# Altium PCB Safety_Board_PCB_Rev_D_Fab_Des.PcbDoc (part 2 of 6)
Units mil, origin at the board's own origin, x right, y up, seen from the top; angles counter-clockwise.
Board outline 11000 x 4400 mil, 6 copper layers (L1-TOP, L2-Plane, L3-Signal, L4-Signal, L5-Plane, L6-BOT); 712 components, 540 nets, 2214 pads, 875 vias.
Unrouted connection lines stored in the file: 3.
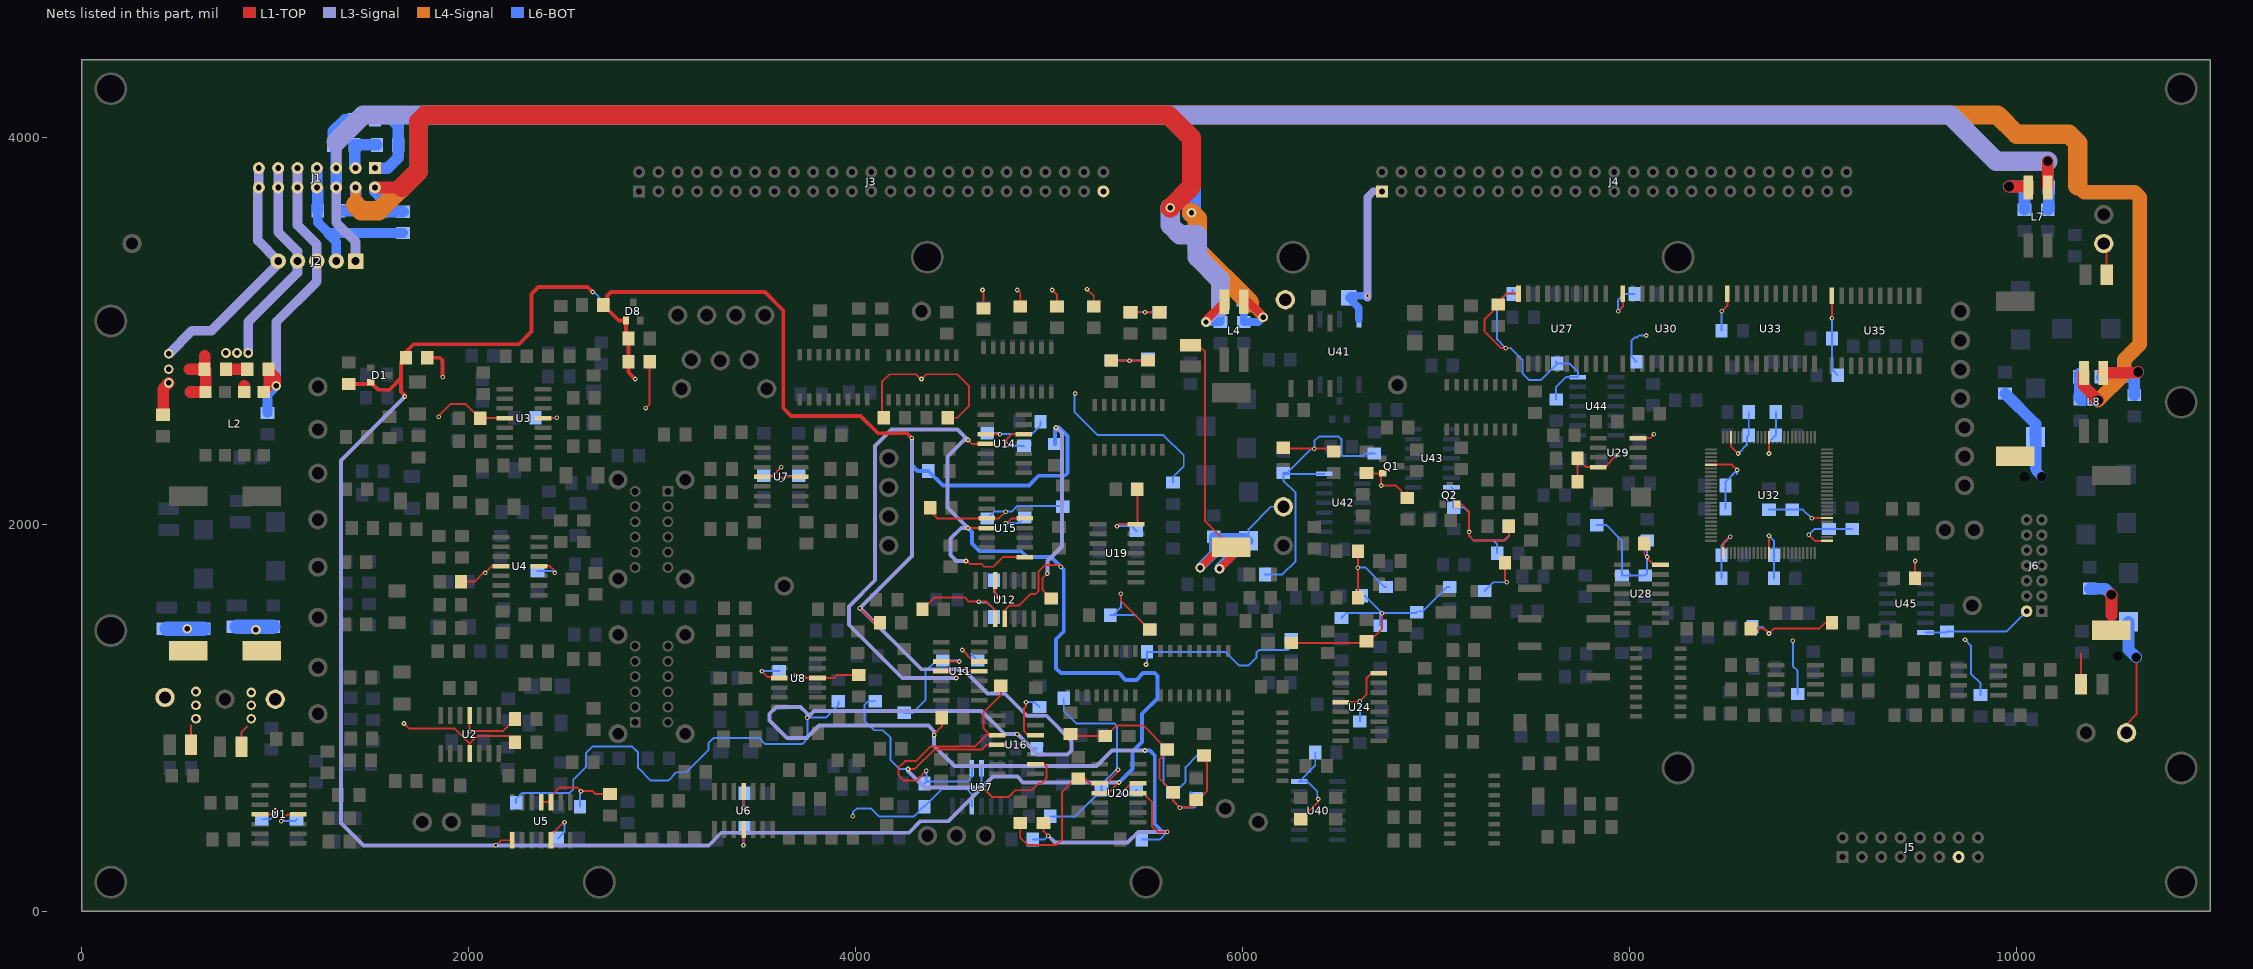
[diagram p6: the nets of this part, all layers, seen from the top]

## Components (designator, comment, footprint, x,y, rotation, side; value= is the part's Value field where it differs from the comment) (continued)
R348 "2000" 1206 7720,1330 r0 bottom locked (schematic designator R154)
R349 "2000" 1206 7720,1211.26 r0 bottom locked (schematic designator R156)
R350 "205" 1206 7760,935 r180 bottom locked (schematic designator R47)
R351 "205" 1206 7760,815 r180 bottom locked (schematic designator R46)
R352 "205" 1206 7850,555 r180 bottom locked (schematic designator R45)
R353 "205" 1206 7850,435 r180 bottom locked (schematic designator R44)
R354 "10000" 1206 7830,2050 r270 bottom locked (schematic designator R179)
R355 "10000" 1206 7960,1680 r90 bottom locked (schematic designator R150)
R356 "100" 1206 7960,1390 r270 bottom locked (schematic designator R158)
R357 "100" 1206 8050,2380 r90 bottom locked (schematic designator R212)
R358 "10000" 1206 8090,1970 r270 bottom locked (schematic designator R188)
R359 "10000" 1206 8090,2840 r180 bottom locked (schematic designator R223)
R360 "100" 1206 8120,2670 r270 bottom locked (schematic designator R242)
R361 "10000" 1206 8080,1680 r90 bottom locked (schematic designator R153)
R362 "100" 1206 8080,1390 r270 bottom locked (schematic designator R159)
R363 "0_jumper" 1206 8697.96,1256.92 r0 bottom locked (schematic designator R134)
R364 "2000" 1206 8517.96,1076.92 r270 bottom locked (schematic designator R155)
R365 "10000" 1206 8580,1470 r0 bottom locked (schematic designator R326)
R366 "0_jumper" 1206 8747.96,1076.92 r90 bottom locked (schematic designator R132)
R367 "100" 1206 8800,2840 r180 bottom locked (schematic designator R240)
R368 "6810" 1206 8870,1540 r180 bottom locked (schematic designator R329)
R369 "0_jumper" 1206 8867.96,1066.92 r90 bottom locked (schematic designator R128)
R370 "0_jumper" 1206 8947.96,1286.92 r90 bottom locked (schematic designator R137)
R371 "10000" 1206 9020,2770 r0 bottom locked (schematic designator R221)
R372 "6810" 1206 9100,1490 r180 bottom locked (schematic designator R272)
R373 "0_jumper" 1206 9177.96,1246.92 r180 bottom locked (schematic designator R136)
R374 "0_jumper" 1206 9210,2920 r0 bottom locked (schematic designator R361)
R375 "0_jumper" 1206 9177.96,1131.92 r180 bottom locked (schematic designator R135)
R376 "0_jumper" 1206 9430,2920 r180 bottom locked (schematic designator R344)
R377 "0_jumper" 1206 9637.96,1256.92 r0 bottom locked (schematic designator R144)
R378 "2000" 1206 9462.96,1071.92 r270 bottom locked (schematic designator R157)
R379 "0_jumper" 1206 9692.96,1071.92 r90 bottom locked (schematic designator R142)
R380 "0_jumper" 1206 9812.96,1061.92 r90 bottom locked (schematic designator R138)
R381 "0_jumper" 1206 9892.96,1281.92 r90 bottom locked (schematic designator R147)
R382 "3.01" 1206 9940,2730 r270 bottom locked (schematic designator R18)
R383 "0_jumper" 1206 10040,3570 r270 bottom locked (schematic designator R8)
R384 "0_jumper" 1206 10117.96,1246.92 r180 bottom locked (schematic designator R146)
R385 "0_jumper" 1206 10122.96,1131.92 r180 bottom locked (schematic designator R145)
R386 "0_jumper" 1206 10160,3570 r270 bottom locked (schematic designator R6)
R387 "249" 1206 10300,3440 r270 bottom locked (schematic designator R405)
R388 "0_jumper" 1206 10330,2590 r270 bottom locked (schematic designator R4)
R389 "3.01" 1206 10377.96,1721.92 r270 bottom locked (schematic designator R17)
R390 "249" 1206 10337.96,1391.92 r270 bottom locked (schematic designator R404)
R391 "0_jumper" 1206 10607.96,2611.92 r270 bottom locked (schematic designator R3)
SW1 "MSS420004" MSS420004 2944.65,1973.11 r270 top locked
SW2 "MSS420004" MSS420004 2944.65,1173.11 r90 top locked
SW3 "TL6120AF300QG" SWITCH_TL6120AF300QG 7660,1590 r270 top locked
SW4 "TL6120AF300QG" SWITCH_TL6120AF300QG 7660,1290 r90 top locked
TP1 "TP_5006" TP_COMPACT 260,3450 r0 top locked (schematic designator TP54)
TP2 "TP_5005" TP_COMPACT 430,1105 r0 top locked
TP3 "TP_5006" TP_COMPACT 740,1095 r0 top locked (schematic designator TP6)
TP4 "TP_5005" TP_COMPACT 1000,1095 r0 top locked (schematic designator TP1)
TP5 "TP_5009" TP_COMPACT 1220,2710 r0 top locked (schematic designator TP11)
TP6 "TP_5008" TP_COMPACT 1220,2490 r0 top locked (schematic designator TP13)
TP7 "TP_5009" TP_COMPACT 1220,2263.11 r0 top locked (schematic designator TP12)
TP8 "TP_5008" TP_COMPACT 1220,2023.11 r0 top locked (schematic designator TP14)
TP9 "TP_5009" TP_COMPACT 1220,1778.11 r0 top locked (schematic designator TP15)
TP10 "TP_5008" TP_COMPACT 1220,1518.11 r0 top locked (schematic designator TP17)
TP11 "TP_5009" TP_COMPACT 1220,1260 r0 top locked (schematic designator TP16)
TP12 "TP_5008" TP_COMPACT 1220,1020 r0 top locked (schematic designator TP18)
TP13 "TP_5007" TP_COMPACT 1760,460 r90 top locked (schematic designator TP28)
TP14 "TP_5007" TP_COMPACT 1910,460 r90 top locked (schematic designator TP31)
TP15 "TP_5007" TP_COMPACT 3080,3080 r0 top locked (schematic designator TP25)
TP16 "TP_5007" TP_COMPACT 3100,2700 r0 top locked (schematic designator TP48)
TP17 "TP_5007" TP_COMPACT 3230,3080 r0 top locked (schematic designator TP19)
TP18 "TP_5007" TP_COMPACT 3150,2850 r0 top locked (schematic designator TP41)
TP19 "TP_5007" TP_COMPACT 3300,2845 r0 top locked (schematic designator TP44)
TP20 "TP_5007" TP_COMPACT 3380,3080 r0 top locked (schematic designator TP35)
TP21 "TP_5007" TP_COMPACT 3530,3080 r0 top locked (schematic designator TP38)
TP22 "TP_5007" TP_COMPACT 3450,2850 r0 top locked (schematic designator TP23)
TP23 "TP_5007" TP_COMPACT 3540,2700 r0 top locked (schematic designator TP49)
TP24 "TP_5006" TP_COMPACT 3630,1680 r0 top locked (schematic designator TP32)
TP25 "TP_5007" TP_COMPACT 4170,2340 r0 top locked (schematic designator TP7)
TP26 "TP_5007" TP_COMPACT 4170,2190 r0 top locked (schematic designator TP21)
TP27 "TP_5007" TP_COMPACT 4170,2040 r0 top locked (schematic designator TP34)
TP28 "TP_5007" TP_COMPACT 4170,1890 r0 top locked (schematic designator TP37)
TP29 "TP_5006" TP_COMPACT 4340,3100 r0 top locked (schematic designator TP27)
TP30 "TP_5007" TP_COMPACT 4370,390 r0 top locked (schematic designator TP22)
TP31 "TP_5007" TP_COMPACT 4520,390 r0 top locked (schematic designator TP40)
TP32 "TP_5007" TP_COMPACT 4670,390 r0 top locked (schematic designator TP43)
TP33 "TP_5006" TP_COMPACT 5910,530 r0 top locked (schematic designator TP51)
TP34 "TP_5006" TP_COMPACT 6080,460 r0 top locked (schematic designator TP52)
TP35 "TP_5006" TP_COMPACT 6220,3160 r0 top locked (schematic designator TP55)
TP36 "TP_5005" TP_COMPACT 6210,2090 r90 top locked (schematic designator TP5)
TP37 "TP_5006" TP_COMPACT 6210,1890 r0 top locked (schematic designator TP10)
TP38 "TP_5006" TP_COMPACT 6800,2720 r180 top locked (schematic designator TP29)
TP39 "TP_5007" TP_COMPACT 9630,1970 r0 top locked (schematic designator TP30)
TP40 "TP_5007" TP_COMPACT 9710,3100 r0 top locked (schematic designator TP20)
TP41 "TP_5007" TP_COMPACT 9710,2950 r0 top locked (schematic designator TP26)
TP42 "TP_5007" TP_COMPACT 9710,2800 r0 top locked (schematic designator TP46)
TP43 "TP_5007" TP_COMPACT 9710,2650 r0 top locked (schematic designator TP47)
TP44 "TP_5007" TP_COMPACT 9730,2500 r0 top locked (schematic designator TP24)
TP45 "TP_5007" TP_COMPACT 9730,2350 r0 top locked
TP46 "TP_5007" TP_COMPACT 9730,2200 r0 top locked (schematic designator TP42)
TP47 "TP_5007" TP_COMPACT 9780,1970 r0 top locked (schematic designator TP33)
TP48 "TP_5006" TP_COMPACT 9770,1580 r0 top locked (schematic designator TP53)
TP49 "TP_5006" TP_COMPACT 10357.97,921.92 r0 top locked (schematic designator TP8)
TP50 "TP_5006" TP_COMPACT 10450,3600 r0 top locked (schematic designator TP9)
TP51 "TP_5005" TP_COMPACT 10450,3450 r90 top locked (schematic designator TP4)
TP52 "TP_5005" TP_COMPACT 10567.97,921.92 r0 top locked (schematic designator TP3)
U1 "OPA4277UA" SOIC_14_Narrow 1020,500 r270 top locked (schematic designator U29)
U2 "OPA4277UA" SOIC_14_Narrow 2004.65,913.11 r0 top locked (schematic designator U8)
U3 "OPA4277UA" SOIC_14_Narrow 2284.65,2548.11 r270 top locked (schematic designator U5)
U4 "OPA4277UA" SOIC_14_Narrow 2264.65,1783.11 r270 top locked (schematic designator U6)
U5 "LM339DR2G" SOIC_14_Narrow 2375,465 r180 top locked (schematic designator U31)
U6 "OPA4277UA" SOIC_14_Narrow 3420,520 r0 top locked (schematic designator U41)
U7 "OPA4277UA" SOIC_14_Narrow 3615,2245 r270 top locked (schematic designator U35)
U8 "OPA4277UA" SOIC_14_Narrow 3703.43,1205 r270 top locked (schematic designator U7)
U9 "TLP281-4" SOIC_16_C5.85 3885,2760 r180 top locked (schematic designator U24)
U10 "TLP281-4" SOIC_16_C5.85 4345,2758 r180 top locked (schematic designator U25)
U11 "LM339DR2G" SOIC_14_Narrow 4540,1240.12 r270 top locked (schematic designator U33)
U12 "LM339DR2G" SOIC_14_Narrow 4770,1610 r0 top locked (schematic designator U39)
U13 "TLP281-4" SOIC_16_C5.85 4835,2795 r180 top locked (schematic designator U18)
U14 "LM339DR2G" SOIC_14_Narrow 4770,2415 r270 top locked (schematic designator U32)
U15 "LM339DR2G" SOIC_14_Narrow 4775,1980 r270 top locked (schematic designator U42)
U16 "LM339DR2G" SOIC_14_Narrow 4830,860 r270 top locked (schematic designator U36)
U17 "TLP281-4" SOIC_16_C5.85 5270,1230 r0 top locked (schematic designator U40)
U18 "TLP281-4" SOIC_16_C5.85 5410,2500 r180 top locked (schematic designator U19)
U19 "M74HC14RM13TR" SOIC_14_Narrow 5350,1850 r270 top locked (schematic designator U26)
U20 "LM339DR2G" SOIC_14_Narrow 5360,610 r270 top locked (schematic designator U38)
U21 "TLP281-4" SOIC_16_C5.85 5750,1230 r0 top locked (schematic designator U34)
U22 "TLP281-4" SOIC_16_C5.85 6090,850 r270 top locked (schematic designator U28)
U23 "PS710EL-1A-A" SO_6_254P 6400,2870 r0 top locked (schematic designator U17)
U24 "DS26LS32ACM" SOIC_16_NARROW 6605,1055 r270 top locked (schematic designator U4)
U25 "TLP281-4" SOIC_16_C5.85 7230,2605 r0 top locked (schematic designator U15)
U26 "TLP281-4" SOIC_16_C5.85 7185,525 r90 top locked (schematic designator U3)
U27 "M74HCT541M1R" SOIC_20_WIDE 7650,3010 r0 top locked (schematic designator U44)
U28 "M74HC14RM13TR" SOIC_14_Narrow 8060,1640 r270 top locked (schematic designator U14)
U29 "TS555IDT" SOIC_8_NARROW 7939.96,2370.04 r90 top locked (schematic designator U9)
U30 "M74HCT541M1R" SOIC_20_WIDE 8190,3010 r0 top locked (schematic designator U45)
U31 "TLP281-4" SOIC_16_C5.85 8147.96,1181.92 r270 top locked (schematic designator U11)
U32 "XC9572-15TQ100C" TQ100 8720,2150 r0 top locked (schematic designator U10)
U33 "M74HCT541M1R" SOIC_20_WIDE 8730,3010 r0 top locked (schematic designator U43)
U34 "MAX1232ESA+" SOIC_8_NARROW 8857.96,1196.92 r90 top locked (schematic designator U12)
U35 "M74HCT541M1R" SOIC_20_WIDE 9270,3000 r0 top locked (schematic designator U46)
U36 "MAX1232ESA+" SOIC_8_NARROW 9802.96,1191.92 r90 top locked (schematic designator U13)
U37 "LM339DR2G" SOIC_14_Narrow 4650,640 r0 bottom locked (schematic designator U47)
U38 "TLP281-4" SOIC_16_C5.85 4835,2810 r0 bottom locked (schematic designator U23)
U39 "TLP281-4" SOIC_16_C5.85 5410,2500 r0 bottom locked (schematic designator U20)
U40 "M74HC14RM13TR" SOIC_14_Narrow 6390,520 r270 bottom locked (schematic designator U30)
U41 "PS710EL-1A-A" SO_6_254P 6450,2890 r180 bottom locked (schematic designator U16)
U42 "M74HC14RM13TR" SOIC_14_Narrow 6520,2110 r270 bottom locked (schematic designator U21)
U43 "M74HC14RM13TR" SOIC_14_Narrow 6980,2340 r90 bottom locked (schematic designator U27)
U44 "M74HC14RM13TR" SOIC_14_Narrow 7830,2610 r270 bottom locked (schematic designator U22)
U45 "M74HC14RM13TR" SOIC_14_Narrow 9430,1590 r90 bottom locked (schematic designator U37)

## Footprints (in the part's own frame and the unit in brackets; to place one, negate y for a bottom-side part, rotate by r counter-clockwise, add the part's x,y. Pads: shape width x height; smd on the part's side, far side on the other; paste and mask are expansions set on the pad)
1-5499923-0 [mil] "Header, 50 pin, male, 2x25, shrouded, latch, vertical"
  rect 62x62 hole 30: 1(0,0)
  round 62 hole 30: 2(100,0) 3(0,-100) 4(100,-100) 5(0,-200) 6(100,-200) 7(0,-300) 8(100,-300) 9(0,-400) 10(100,-400) 11(0,-500) 12(100,-500) 13(0,-600) 14(100,-600) 15(0,-700) 16(100,-700) 17(0,-800) 18(100,-800) 19(0,-900) 20(100,-900) 21(0,-1000) 22(100,-1000) 23(0,-1100) 24(100,-1100) 25(0,-1200) 26(100,-1200) 27(0,-1300) 28(100,-1300) 29(0,-1400) 30(100,-1400) 31(0,-1500) 32(100,-1500) 33(0,-1600) 34(100,-1600) 35(0,-1700) 36(100,-1700) 37(0,-1800) 38(100,-1800) 39(0,-1900) 40(100,-1900) 41(0,-2000) 42(100,-2000) 43(0,-2100) 44(100,-2100) 45(0,-2200) 46(100,-2200) 47(0,-2300) 48(100,-2300) 49(0,-2400) 50(100,-2400)
  silkscreen extent -150,-2850 250,450
22-23-2051 [mil] "Header, 5 pin male, vertical (IRTF power connector)"
  rect 80x80 hole 40: 1(0,-200)
  round 80 hole 40: 2(0,-100) 3(0,0) 4(0,100) 5(0,200)
  silkscreen extent -130,-260 130,260
1206 [mm]
  rect 1.6x1.8 smd: 1(-1.4,0) 2(1.4,0)
  silkscreen extent -2.6,-1.3 2.6,1.3
1210 [mm]
  rect 1.6x2.7 smd: 1(-1.4,0) 2(1.4,0)
  silkscreen extent -2.6,-1.75 2.6,1.75
5000_inductor [mil] "Inductor, Common Mode"
  rect 125x50 smd: 1(-150,50) 2(-150,-50) 3(150,-50) 4(150,50)
  silkscreen extent -230,-125 230,170
5000_INDUCTOR [mil] "Inductor, Common Mode"
  rect 125x50 smd: 1(-150,50) 2(-150,-50) 3(150,-50) 4(150,50)
  silkscreen extent -230,-125 230,170
8532_inductor [mil] "Inductor, 8532 series"
  rect 100x200 smd: 1(-400,0) 2(400,0)
  silkscreen extent -470,-180 470,180
5499922-2 [mil] "Header, 14 pin, male, 2x7, shrouded, latch, vertical"
  rect 62x62 hole 30: 1(0,0)
  round 62 hole 30: 2(100,0) 3(0,-100) 4(100,-100) 5(0,-200) 6(100,-200) 7(0,-300) 8(100,-300) 9(0,-400) 10(100,-400) 11(0,-500) 12(100,-500) 13(0,-600) 14(100,-600)
  silkscreen extent -150,-1050 250,450
5499922-3 [mil] "Header, 16 pin, male, 2x8, shrouded, latch, vertical"
  rect 62x62 hole 30: 1(0,0)
  round 62 hole 30: 2(100,0) 3(0,-100) 4(100,-100) 5(0,-200) 6(100,-200) 7(0,-300) 8(100,-300) 9(0,-400) 10(100,-400) 11(0,-500) 12(100,-500) 13(0,-600) 14(100,-600) 15(0,-700) 16(100,-700)
  silkscreen extent -150,-1150 250,450
CAP_EIA_6032 [mm]
  rect 2.6x2.5 smd: 1(-2.5,0) 2(2.5,0)
  silkscreen extent -5.2,-1.78 4.2,1.78
CAP_EIA_7343 [mm]
  rect 2.6x2.5 smd: 1(-3.2,0) 2(3.2,0)
  silkscreen extent -5.9,-2.45 4.9,2.45
"DO-214AA (SMB) & MARKING" [mm]
  rect 1.7x2.2 smd: A(-2.1,0) K(2.1,0)
  silkscreen extent -3.17,-2.03 3.17,3.68
"DO-214AC (SMA)" [mil] "SMA"
  rect 80x80 smd: A(-78.5,0) K(78.5,0)
  silkscreen extent -130,-60 130,60
HDR_87831-1420 [mil] "Header, 7x2, straight, shroud, common use for JTAG"
  rect 60x60 hole 28: 1(0,0)
  round 60 hole 28: 2(78.74,0) 3(0,-78.74) 5(0,-157.48) 6(78.74,-157.48) 7(0,-236.22) 8(78.74,-236.22) 9(0,-314.96) 10(78.74,-314.96) 11(0,-393.7) 12(78.74,-393.7) 13(0,-472.44) 14(78.74,-472.44)
  round 59.06 hole 28: 4(78.74,-78.74)
  silkscreen extent -98,-571 177,98
LED_1210 [mm] "LED, 1210 case"
  rect 1.6x2.7 smd: A(-1.4,0) K(1.4,0)
  silkscreen extent -2.6,-1.78 2.6,1.78
MSS420004 [mm] "Switch, Slide, 4PDT"
  rect 1.422x1.422 hole 0.914: 1(-5,2.15)
  round 1.422 hole 0.914: 2(-3,2.15) 3(-1,2.15) 4(1,2.15) 5(3,2.15) 6(5,2.15) 7(-5,-2.15) 8(-3,-2.15) 9(-1,-2.15) 10(1,-2.15) 11(3,-2.15) 12(5,-2.15)
  round 2.5 hole 1.5: ""(-6.5,4.4) ""(-6.5,-4.4) ""(6.5,4.4) ""(6.5,-4.4)
  silkscreen extent -8,-5.5 8,5.5
SO_6_254P [mm] "Surface mount, 6 pin, 2.54mm spacing"
  rect 0.65x2.2 smd: 1(-3.81,-4.3) 2(-1.27,-4.3) 3(1.27,-4.3) 4(1.27,4.3) 5(-1.27,4.3) 6(-3.81,4.3)
  silkscreen extent -6,-4.42 3.5,2.8
SOIC_8_NARROW [mm] "8 pin Narrow SOIC"
  rect 0.6x2.2 smd: 1(-1.905,-2.6) 2(-0.635,-2.6) 3(0.635,-2.6) 4(1.905,-2.6) 5(1.905,2.6) 6(0.635,2.6) 7(-0.635,2.6) 8(-1.905,2.6)
  silkscreen extent -2.88,-2.72 2.5,1.1
SOIC_14_Narrow [mm] "14 pin Narrow SOIC"
  rect 0.6x2.2 smd: 1(-3.81,-2.5) 2(-2.54,-2.5) 3(-1.27,-2.5) 4(0,-2.5) 5(1.27,-2.5) 6(2.54,-2.5) 7(3.81,-2.5) 8(3.81,2.5) 9(2.54,2.5) 10(1.27,2.5) 11(0,2.5) 12(-1.27,2.5) 13(-2.54,2.5) 14(-3.81,2.5)
  silkscreen extent -4.78,-2.62 4.38,1
SOIC_16_C5.85 [mm]
  rect 0.6x1.55 smd: 1(-4.445,-2.925) 2(-3.175,-2.925) 3(-1.905,-2.925) 4(-0.635,-2.925) 5(0.635,-2.925) 6(1.905,-2.925) 7(3.175,-2.925) 8(4.445,-2.925) 9(4.445,2.925) 10(3.175,2.925) 11(1.905,2.925) 12(0.635,2.925) 13(-0.635,2.925) 14(-1.905,2.925) 15(-3.175,2.925) 16(-4.445,2.925)
  silkscreen extent -5.4,-3.05 5,1.75
SOIC_16_NARROW [mm] "16 pin Narrow SOIC"
  rect 0.6x2.2 smd: 1(-4.445,-2.5) 2(-3.175,-2.5) 3(-1.905,-2.5) 4(-0.635,-2.5) 5(0.635,-2.5) 6(1.905,-2.5) 7(3.175,-2.5) 8(4.445,-2.5) 9(4.445,2.5) 10(3.175,2.5) 11(1.905,2.5) 12(0.635,2.5) 13(-0.635,2.5) 14(-1.905,2.5) 15(-3.175,2.5) 16(-4.445,2.5)
  silkscreen extent -5.42,-2.62 5,1
SOIC_20_WIDE [mm] "Small Outline; 20 Leads; Body Width 7.5 mm; Pitch 1.27 mm"
  rect 0.6x2.2 smd: 1(-5.715,-4.6) 2(-4.445,-4.6) 3(-3.175,-4.6) 4(-1.905,-4.6) 5(-0.635,-4.6) 6(0.635,-4.6) 7(1.905,-4.6) 8(3.175,-4.6) 9(4.445,-4.6) 10(5.715,-4.6) 11(5.715,4.6) 12(4.445,4.6) 13(3.175,4.6) 14(1.905,4.6) 15(0.635,4.6) 16(-0.635,4.6) 17(-1.905,4.6) 18(-3.175,4.6) 19(-4.445,4.6) 20(-5.715,4.6)
  silkscreen extent -6.69,-4.72 6.53,3.1
SOT23 [mm]
  rect 0.85x1 smd: 1(-0.95,-1.2) 2(0.95,-1.2) 3(0,1.2)
  silkscreen extent -2.05,-1.32 1.28,1.2
SWITCH_TL6120AF300QG [mm] "Switch, Tactile, SPST, NO"
  rect 1x3.1 smd: 1(2,4.5) 2(-2,4.5) 3(2,-4.5) 4(-2,-4.5)
  silkscreen extent -3.6,-3.6 3.6,3.6
TP_COMPACT [mil] "5005-5009 Compact Test Points"
  round 100 hole 63: 1(0,0)
  silkscreen extent -65,-65 65,65
TQ100 [mm]
  rect 1.6x0.3 smd: 1(-7.6,6) 2(-7.6,5.5) 3(-7.6,5) 4(-7.6,4.5) 5(-7.6,4) 6(-7.6,3.5) 7(-7.6,3) 8(-7.6,2.5) 9(-7.6,2) 10(-7.6,1.5) 11(-7.6,1) 12(-7.6,0.5) 13(-7.6,0) 14(-7.6,-0.5) 15(-7.6,-1) 16(-7.6,-1.5) 17(-7.6,-2) 18(-7.6,-2.5) 19(-7.6,-3) 20(-7.6,-3.5) 21(-7.6,-4) 22(-7.6,-4.5) 23(-7.6,-5) 24(-7.6,-5.5) 25(-7.6,-6) 51(7.6,-6) 52(7.6,-5.5) 53(7.6,-5) 54(7.6,-4.5) 55(7.6,-4) 56(7.6,-3.5) 57(7.6,-3) 58(7.6,-2.5) 59(7.6,-2) 60(7.6,-1.5) 61(7.6,-1) 62(7.6,-0.5) 63(7.6,0) 64(7.6,0.5) 65(7.6,1) 66(7.6,1.5) 67(7.6,2) 68(7.6,2.5) 69(7.6,3) 70(7.6,3.5) 71(7.6,4) 72(7.6,4.5) 73(7.6,5) 74(7.6,5.5) 75(7.6,6)
  rect 0.3x1.6 smd: 26(-6,-7.6) 27(-5.5,-7.6) 28(-5,-7.6) 29(-4.5,-7.6) 30(-4,-7.6) 31(-3.5,-7.6) 32(-3,-7.6) 33(-2.5,-7.6) 34(-2,-7.6) 35(-1.5,-7.6) 36(-1,-7.6) 37(-0.5,-7.6) 38(0,-7.6) 39(0.5,-7.6) 40(1,-7.6) 41(1.5,-7.6) 42(2,-7.6) 43(2.5,-7.6) 44(3,-7.6) 45(3.5,-7.6) 46(4,-7.6) 47(4.5,-7.6) 48(5,-7.6) 49(5.5,-7.6) 50(6,-7.6) 76(6,7.6) 77(5.5,7.6) 78(5,7.6) 79(4.5,7.6) 80(4,7.6) 81(3.5,7.6) 82(3,7.6) 83(2.5,7.6) 84(2,7.6) 85(1.5,7.6) 86(1,7.6) 87(0.5,7.6) 88(0,7.6) 89(-0.5,7.6) 90(-1,7.6) 91(-1.5,7.6) 92(-2,7.6) 93(-2.5,7.6) 94(-3,7.6) 95(-3.5,7.6) 96(-4,7.6) 97(-4.5,7.6) 98(-5,7.6) 99(-5.5,7.6) 100(-6,7.6)
  silkscreen extent -12.7,-12.7 12.7,12.7
ZJYS51R5-M4PA_INDCUTOR [mm] "Inductor, CM, 4 line"
  rect 1.6x1.6 smd: 1(-3.81,-4.15) 2(-1.27,-4.15) 3(1.27,-4.15) 4(3.81,-4.15) 5(3.81,4.15) 6(1.27,4.15) 7(-1.27,4.15) 8(-3.81,4.15)
  silkscreen extent -5.5,-4.32 5.5,3.05

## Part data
C1 C2 C3 C5 C18 C19 C25 C26 C27 C28 C29 C30 C31 C32 C34 C35 C40 C42 C47 C70 C78 C79 C80 C86 C88 C89 C90 C104 C105 C108 C109 C112 C114 C115 C117 C119 C121 C122 C124 C125 C126 C127 C129 C130 C131 C132 C133 C135 C136 C138 C139 C141 C144 C145 C148 C149 C150 C154 C158 C162: "Ceramic Chip Capacitor, 1uF, 50V, 10%, X7R"
C4 C6 C7 C9 C11 C22 C61 C62: "Ceramic Chip Capacitor, 0.022uF, 50V, 10%, X7R"
C8 C13 C66 C82: "Ceramic Chip Capacitor, 0.068uF, 50V, 10%, X7R"
C10 C12 C15 C16 C23 C24 C33 C36 C39 C41 C43 C51 C52 C53 C54 C55 C56 C57 C58 C59 C60 C67 C68 C71 C74 C75 C76 C77 C81 C83 C84 C85 C87 C91 C92 C93 C94 C95 C96 C97 C98 C99 C100 C101 C102 C103 C106 C107 C116 C118 C120 C123 C128 C134 C137 C140 C142 C143 C146 C147 C151 C152 C153 C155 C156 C160: "Ceramic Chip Capacitor, 0.1uF, 50V, 10%, X7R"
C14 C72: "Ceramic Chip Capacitor, 0.22uF, 50V, 10%, X7R"
C17 C21 C64 C73: "Ceramic Chip Capacitor, 2200pF, 50V, 5%, X7R"
C20 C63 C65 C69: "Ceramic Chip Capacitor, 0.33uF, 50V, 10%, X7R"
C37: "Ceramic Chip Capacitor, 0.01uF, 50V, 10%, X7R"
C38: "CAP TANTALUM, 10UF, 25V, 10%"
C44 C45 C48 C49: "Ceramic Chip Capacitor, 22uF, 25V, 20%, X5R"
C46 C50 C111 C113 C159 C161 C164 C165: "CAP TANTALUM, 100UF, 25V, 10%"
C110 C157 C163: "CAP TANTALUM 470UF 10V 10%"
D1 D8: "5V Shunt Voltage Reference, 1%"
D2 D3 D4 D5 D6 D7 D9 D13 D14 D15 D16 D17 D18 D20 D21 D23 D25 D27 D29 D30: "RECT FAST RECOVERY 200V 1A"
D10 D11 D12 D28: "TVS 400W 26V BIDIRECT SMA"
D19 D22 D24 D26: "TVS 400W 10V BIDIRECT SMA"
DS1 DS2 DS3 DS4 DS5 DS6 DS7: "LED, Green, Dome, 1210 SMD"
J1: "Header, 14-Pin, Dual row, Straight, Latch, Shroud"
J2: library part IRTF_STD_POWER, "Header, 5 position, single row, male, straight"
J3 J4: "Header, 50-Pin, Dual Row, Shrouded, Straight, Male, Shroud"
J5: "Header, 16-Pin, Dual row, Straight, Latch, Shroud"
J6: "Header, 14-Pin, Dual row, Straight, Shroud"
L1 L3: "Inductor, 5.6mH, 180mA, 15%"
L2: "Inductor, CM, 4 terminal, 500mA"
L4 L7 L8: "Inductor, CM, 1mH, 700mA, 50%"
L5 L6 L9: "Inductor, 1.2mH, 370mA, 15%"
Q1 Q2: "PNP Switching Transistor"
Q3: "NPN Switching Transistor"
R1 R3 R4 R8 R29 R49 R50 R54 R55 R63 R67 R68 R81 R114 R138 R139 R140 R141 R148 R149 R151 R153 R154 R155 R159 R160 R161 R172 R173 R177 R178 R179 R180 R183 R184 R186 R187 R189 R192 R194 R197 R198 R200 R201 R202 R203 R208 R210 R213 R228 R235 R237 R238 R241 R264 R275 R285 R292 R306 R307 R318 R319 R320 R321 R327 R329 R330 R331 R332 R333 R335 R343 R344 R363 R366 R369 R370 R373 R374 R375 R376 R377 R379 R380 R381 R383 R384 R385 R386 R388 R391: "Thick Film Chip Resistor, 0 Ohm, 1206 Size, 0.25 W"
R2 R6 R7 R26 R47 R51 R53 R56 R57 R58 R59 R60 R61 R64 R69 R76 R77 R85 R88 R90 R99 R106 R113 R117 R128 R129 R130 R132 R134 R135 R136 R142 R143 R146 R156 R158 R170 R171 R175 R176 R181 R182 R185 R196 R204 R205 R206 R207 R209 R219 R239 R247 R248 R252 R266 R276 R279 R283 R287 R288 R295 R298 R308 R312 R316 R317 R322 R323 R324 R328 R337 R340 R341 R345 R354 R355 R358 R359 R361 R365 R371: "Thick Film Chip Resistor, 10k Ohm, 1% Tolerance, 1206 Size, 0.25 W"
R5 R35 R199 R231 R258 R263: "Thick Film Chip Resistor, 20k Ohm, 1% Tolerance, 1206 Size, 0.25 W"
R9 R10 R11 R12 R13 R14 R15 R16: "Thick Film Chip Resistor, 47.5k Ohm, 1% Tolerance, 1206 Size, 0.25 W"
R17 R23 R38 R46 R105 R110 R119 R120 R121 R122 R144 R150 R234 R259 R284 R296 R299 R304 R305 R311: "Thick Film Chip Resistor, 4.87k Ohm, 1% Tolerance, 1206 Size, 0.25 W"
R18 R24 R30 R33 R39 R48 R66 R70 R75 R214 R216 R226 R249 R262: "Thick Film Chip Resistor, 200k Ohm, 1% Tolerance, 1206 Size, 0.25 W"
R19 R20 R21 R41 R52 R220 R223 R224 R230 R232 R242 R256: "Thick Film Chip Resistor, 301k Ohm, 1% Tolerance, 1206 Size, 0.25 W"
R22 R42 R71 R127 R133 R137 R174 R229 R309 R313 R325 R368 R372: "Thick Film Chip Resistor, 6.81k Ohm, 1% Tolerance, 1206 Size, 0.25 W"
R25 R34 R222 R245: "Thick Film Chip Resistor, 56.2k Ohm, 1% Tolerance, 1206 Size, 0.25 W"
R27 R74 R83 R86 R89 R94 R96 R97 R98 R103 R115 R169 R217 R265 R267 R270 R271 R278 R289: "Thick Film Chip Resistor, 100k Ohm, 1% Tolerance, 1206 Size, 0.25 W"
R28 R32 R40 R62 R82 R93 R95 R101 R108 R111 R112 R116 R118 R272 R274 R280 R286 R290 R291 R294 R297 R348 R349 R364 R378: "Thick Film Chip Resistor, 2k Ohm, 1% Tolerance, 1206 Size, 0.25 W"
R31 R233: "Thick Film Chip Resistor, 33.2k Ohm, 1% Tolerance, 1206 Size, 0.25 W"
R36 R43 R80 R109 R123 R124 R125 R126 R131 R147 R157 R164 R215 R227 R250 R255 R261 R300 R303 R314 R315 R326 R338 R339 R342 R346 R347 R356 R357 R360 R362 R367: "Thick Film Chip Resistor, 100 Ohm, 1% Tolerance, 1206 Size, 0.25 W"
R37 R44 R211 R212 R218 R236 R240 R246: "Thick Film Chip Resistor, 68.1k Ohm, 1% Tolerance, 1206 Size, 0.25 W"
R45 R72 R251: "Thick Film Chip Resistor, 40.2k Ohm, 1% Tolerance, 1206 Size, 0.25 W"
R65 R73 R78 R193 R253 R260: "Thick Film Chip Resistor, 1k Ohm, 1% Tolerance, 1206 Size, 0.25 W"
R79 R84 R87 R91 R92 R100 R102 R104 R107 R188 R191 R221 R225 R268 R269 R273 R277 R281 R282 R293: "Thick Film Chip Resistor, 1.21k Ohm, 1% Tolerance, 1206 Size, 0.25 W"
R145 R152 R301 R310 R334 R336 R387 R390: "Thick Film Chip Resistor, 249 Ohm, 1% Tolerance, 1206 Size, 0.25 W"
R162 R163: "Thick Film Chip Resistor, 4.75k Ohm, 1% Tolerance, 1206 Size, 0.25 W"
R165 R166 R167 R168 R350 R351 R352 R353: "Thick Film Chip Resistor, 205 Ohm, 1% Tolerance, 1206 Size, 0.25 W"
R190 R195: "Thick Film Chip Resistor, 15.8 Ohm, 1% Tolerance, 1206 Size, 0.25 W"
R243 R244 R254 R257: "Thick Film Chip Resistor, 15k Ohm, 1% Tolerance, 1206 Size, 0.25 W"
R302 R382 R389: "Thick Film Chip Resistor, 3.01 Ohm, 1% Tolerance, 1206 Size, 0.25W"
SW1 SW2: "Switch, Slide, 4PDT"
SW3 SW4: "Switch, Tactile, SPST, NO"
TP1 TP3 TP24 TP29 TP33 TP34 TP35 TP37 TP38 TP48 TP49 TP50: "Black, Compact Test Point, Thru Hole, Loop"
TP2 TP4 TP36 TP51 TP52: "Red, Compact Test Point, Thru Hole, Loop"
TP5 TP7 TP9 TP11: "Yellow, Compact Test Point, Thru Hole, Loop"
TP6 TP8 TP10 TP12: "Orange, Compact Test Point, Thru Hole, Loop"
TP13 TP14 TP15 TP16 TP17 TP18 TP19 TP20 TP21 TP22 TP23 TP25 TP26 TP27 TP28 TP30 TP31 TP32 TP39 TP40 TP41 TP42 TP43 TP44 TP45 TP46 TP47: "White, Compact Test Point, Thru Hole, Loop"
U1 U2 U3 U4 U6 U7 U8: "QUAD PRECISION OPAMP 14-SOIC"
U5 U11 U12 U14 U15 U16 U20 U37: "Quad Comparator"
U9 U10 U13 U17 U18 U21 U22 U25 U26 U31 U38 U39: "Photocoupler"
U19 U28 U40 U42 U43 U44 U45: "Hex Schmitt-Trigger Inverter"
U23 U41: "Solid State Relay, 2A, 80V"
U24: "IC LINE RCVR QUAD DIFF"
U27 U30 U33 U35: "Octal Bus Buffer with 3 State Outputs (Non Inverted)"
U29: "IC PRECISION TIMER , CMOS, 8-SOIC"
U32: "XC9500 CPLD with 72 Macrocells, 100-Pin TQFP, Commercial Grade"
U34 U36: "IC MPU SUPERVISORY CIRCUIT 8SOIC"

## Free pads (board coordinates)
  round 170 hole 141: ""(150,150) ""(150,1450) ""(150,3050) ""(150,4250) ""(2675,150) ""(4370,3380) ""(5500,150) ""(6260,3380) ""(8250,740) ""(8250,3380) ""(10850,150) ""(10850,740) ""(10850,2630) ""(10850,4250)

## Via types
v1: diameter 24, hole 12, L1-TOP to L6-BOT, 720 vias
v2: diameter 50, hole 28, L1-TOP to L6-BOT, 138 vias
v3: diameter 28, hole 50, L1-TOP to L6-BOT, 17 vias

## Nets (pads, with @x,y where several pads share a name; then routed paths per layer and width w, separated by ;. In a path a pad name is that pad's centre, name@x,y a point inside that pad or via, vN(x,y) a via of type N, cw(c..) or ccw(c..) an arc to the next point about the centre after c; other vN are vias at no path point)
15V_RTN: C1.2 C2.1 J1.11 J1.12 J2.4 L2.6 | length 1243.4
  L1-TOP w60: C1.2@745.12,2800 C2.1@854.88,2800 ; L2.6@840,2683.39 840,2715
  L3-Signal w50: v2(860,2885) 860,3045 1115,3300 1115,3410 1015,3510 J1.11@1015,3840
  other v2: 745,2885 802,2885
24V: D28.K J4.1 U41.6 | length 840.1
  L3-Signal w40: v1@6645,3170 6645,3690 6675,3720 J4.1@6720,3720
  L6-BOT w40: U41.6@6600,3059.29 6600,3118.5 D28.K@6548.5,3170 6558.5,3180 v1(6645,3180)
24VGND: J3.49 TP35.1
+5_VREF: C19.2 D8.1 R35.2 R46.1 R79.1 R92.1 R100.1 R102.1 R225.1 R258.2 R268.1 R275.1 R277.1 R282.1 R293.1 U11.11 U20.11 | length 15849.9
  L1-TOP w10: v1(4020,1565) 4095,1490 R79.1@4124.88,1490 ; v1(4405,910) 4405,915 4444.88,954.88 R92.1@4444.88,1000.12 ; v1(4565,1240) 4638.31,1240 U11.11@4638.43,1240.12 ; R100.1@4970,454.88 4970,415 v1(4995,390) ; v1(4990,1745) 4965,1720 4965,1660 5009.88,1615.12 R102.1@5010,1615.12 ; U20.11@5458.43,610 5485,610 5530,565 5530,440 5560,410 v1(5610,410)
  L1-TOP w20: R35.2@2694.76,3133.11 2775.12,3052.76 D8.1@2812.6,3052.76 2812.6,2972.28 C19.2@2824.88,2960 R46.1@2824.88,2840 2824.88,2785.12 v1(2860,2750) ; R35.2@2715,3165 2715,3180 2735,3200 3530,3200 3625,3105 3625,2600 3665,2560 4025,2560 4115,2470 4265,2470 v1(4290,2445)
  L3-Signal w15: 4522.19,1250 4528.65,1243.54 v1@4561.46,1243.54
  L3-Signal w20: v1(4290,2445) 4290,1835 v1(4020,1565) 4025,1565 4340,1250 4522.19,1250 ; v1@4561.46,1243.54 4680,1125 4770,1125 4885,1010 4985,1010 5115,880 5115,830 5095,810 4940,810 v1(4835,915) 4770,915 4650,1035 3785,1035 v1(3750,1000) 3750,1020 3715,1055 3590,1055 3555,1020 3555,985 3645,895 3745,895 3810,960 4375,960 4405,930 4405,855 4510,750 5245,750 5325,830 v1(5495,830) ; v1(4990,1745) 4990,1810 5065,1885 5065,2470 v1(5035,2500) ; v1(4995,390) 5030,355 5405,355 5460,410 v1(5610,410)
  L6-BOT w10: R225.1@2244.88,560 2244.88,579.88 2275,610 2520,610 2540,630 2540,680 2605,745 2605,815.96 2639.04,850 2845,850 2875,820 2875,740 2940,675 3030,675 3073,718 3123,718 3240,835 3240,870 3265,895 3500,895 3530,865 3725,865 3750,890 v1(3750,1000) 3845,1000 3910,1065 R258.2@3910,1084.88 ; v1(4835,915) 4910,840 R277.1@4935.12,840 ; R275.1@4915.12,370 4975,370 v1(4995,390) ; R293.1@5480.12,370 5570,370 v1(5610,410)
  L6-BOT w20: v1(4290,2445) 4290,2305 4320,2275 R268.1@4374.88,2275 4449.88,2200 4895,2200 4945,2250 5080,2250 5095,2265 5095,2455 5050,2500 v1(5035,2500) 5030,2495 R282.1@5030,2415.12 ; v1(5495,830) 5520,830 5545,805 5545,450 5585,410 v1(5610,410)
+5V_DIG: C33.2 C36.2 C39.2 C106.2 C116.2 C118.2 C120.2 C123.2 C128.2 C134.2 C137.2 C138.2 C139.2 C140.2 C142.2 C143.2 C145.2 C146.2 C147.2 C148.2 C149.2 C150.2 C151.2 C152.2 C154.2 C155.2 C156.2 C159.1 DS6.A J5.13 J6.2 L6.2 Q1.2 Q2.2 R77.2 R85.2 R113.2 R117.2 R129.2 R130.2 R132.2 R134.2 R135.2 R136.2 R142.1 R143.2 R146.2 R156.2 R158.2 R163.2 R170.2 R176.2 R181.2 R287.2 R288.2 R295.2 R298.2 R308.2 R312.2 R316.2 R317.2 R322.2 R323.2 R324.2 R328.2 R334.2 R336.2 R337.2 R340.2 R341.2 R345.2 R354.2 R355.2 R358.2 R359.2 R361.2 R365.2 R371.2 R382.2 TP51.1 U19.14 U24.4 U24.16 U27.20 U28.14 U29.4 U29.8 U30.20 U32.5 U32.26 U32.38 U32.51 U32.57 U32.88 U32.98 U33.20 U35.20 U40.14 U42.14 U43.14 U44.14 U45.14 | length 18332
  L1-TOP w10: R77.2@4144.88,2550 4144.88,2555.12 4135,2565 4135,2735 4175,2775 4310,2775 4335,2750 v1(4340,2750) 4365,2775 4525,2775 4585,2715 4585,2610 4525,2550 R85.2@4475.12,2550 ; v1(5350,1990) 5360,2000 U19.14@5448.43,2000 5455.12,2006.69 R113.2@5455.12,2180 R113.2@5448.43,2173.31 ; v1(5370,1640) 5370,1605 5520,1455 R117.2@5520,1454.88 ; R129.2@6210,2395.12 6215.12,2390 6455.12,2390 R134.2@6470,2375.12 ; R132.2@6250,1385.12 6630.24,1385.12 R143.2@6640,1394.88 6654.88,1394.88 6720,1460 v1(6720,1540) ; R130.2@6314.88,474.88 R130.2@6300,474.88 6390,564.88 v1(6390,580) ; U24.4@6506.57,1080 6600,1080 6640,1120 6640,1205 6665,1230 U24.16@6703.43,1230 ; R136.2@6595.12,1620 6595,1620.12 v1(6595,1775) 6595.12,1775.12 R135.2@6595.12,1860 ; R142.1@6640,2264.88 6642.28,2262.6 Q1.2@6722.76,2262.6 6715,2254.84 v1(6715,2200) 6790,2200 R146.2@6850,2140 ; R146.2@6850,2135.12 R146.2@6850,2165.35 ; Q2.2@7107.4,2102.76 7132.24,2102.76 7170,2065 7170,1940 7195,1915 7355,1915 7375.12,1935.12 R158.2@7375.12,1990 ; R156.2@7354.88,1800 7354.88,1710.12 v1(7365,1700) ; 7375,2910 7335,2910 7250,2995 7250,3060 7320,3130 7320,3150 7361.1,3191.1 U27.20@7425,3191.1 ; R163.2@7729.96,2340.04 7774.96,2295.04 7869.96,2295.04 v1(7929.96,2355.04) ; C36.2@7730.12,2220 R163.2@7730.12,2339.88 ; v1(7940,3100) 7965,3125 U30.20@7965,3191.1 ; U29.4@8042.32,2445.04 8105.04,2445.04 v1(8125,2465) ; C39.2@8075.12,1900 8075.12,1844.88 v1(8090,1830) 8090,1825 8125,1790 U28.14@8158.43,1790 ; U32.5@8420.79,2307.48 8527.52,2307.48 v1(8555,2280) ; v1(8475,3100) 8505,3130 U33.20@8505,3191.1 ; U32.26@8483.78,1850.79 8483.78,1903.78 8520,1940 v1(8520,1935) ; U32.98@8523.15,2449.21 8523.15,2401.85 v1(8560,2365) ; R170.2@8625.12,1460 8695,1460 v1(8720,1435) 8745,1460 8980,1460 9010,1490 R176.2@9044.88,1490 ; U32.38@8720,1850.79 v1@8720,1945 ; v1(8720,2365) U32.88@8720,2449.21 ; v1(8925,1945) 8956.22,1913.78 U32.51@9019.21,1913.78 ; v1(8940,2030) 8935,2030 8936.89,2031.89 U32.57@9019.21,2031.89 ; v1(9045,3065) U35.20@9045,3181.1 ; v1(9475,1810) 9475,1720.12 R181.2@9475.12,1720 R181.2@9480,1720 ; TP51.1@10450,3450 10465.12,3434.88 DS6.A@10465.12,3290
  L6-BOT w10: v1(5135,2675) 5130,2670 5130,2580 5250,2460 5590,2460 5695,2355 5695,2300 5640,2245 R298.2@5640,2215.12 ; R287.2@5315.12,1530 5444.88,1530 R295.2@5520,1454.88 ; R287.2@5330,1530 5370,1570 v1(5370,1640) ; v1(5350,1990) 5425.12,1990 C106.2@5450,1965.12 ; v1(5500,1275) 5500,1280 5505.12,1285.12 R288.2@5505.12,1340 5910,1340 5980,1270 6030,1270 6070,1310 6070,1335 6085,1350 6235,1350 6250,1365 R312.2@6250,1405.12 ; R308.2@6115.12,1740 6205,1740 6273,1808 6273,2162 6210,2225 C116.2@6210,2264.88 ; C118.2@6374.88,820 6374.88,753.31 U40.14@6291.57,670 6335,670 6385,620 6385,585 v1(6390,580) ; U42.14@6421.57,2260 6214.88,2260 C116.2@6210,2264.88 ; R317.2@6510,1515.12 6534.88,1540 6894.88,1540 R328.2@6900,1545.12 ; v1(6595,1775) 6635,1775 6735.12,1674.88 R323.2@6740,1674.88 ; C120.2@6605,980.12 v1(6605,1085) ; R316.2@6615.12,1630 6630,1630 v1(6720,1540) 6710,1530 R324.2@6710,1475.12 ; R322.2@6680,2364.88 6629.88,2364.88 6617.02,2352.02 6517.98,2352.02 6510,2360 6510,2440 6497,2453 6393,2453 6370,2430 v1(6370,2390) 6355,2390 6229.88,2264.88 C116.2@6210,2264.88 ; R328.2@6910,1550 6930,1550 7055.12,1675.12 R334.2@7070,1675.12 ; U43.14@7078.43,2190 7090,2178.43 C123.2@7090,2085.12 7144.88,2085.12 7170,2060 7170,1940 7195,1915 7350,1915 7375.12,1940.12 R340.2@7375.12,1990 ; R336.2@7250,1655.12 7294.88,1700 v1(7365,1700) ; 7295,1915 7314.88,1895.12 R341.2@7314.88,1850 ; R337.2@7394.88,3200 R337.2@7400,3200 ; R337.2@7394.88,3209.88 R337.2@7394.88,3190 7365,3190 7315,3140 7315,2955 v1(7360,2910) 7385,2910 7445,2850 7445,2780 7480,2745 7540.12,2745 C128.2@7625.12,2830 7690,2830 7731.57,2788.43 U44.14@7731.57,2760 7670,2760 7620,2710 R345.2@7620,2645.12 ; C128.2@7620,2835 C128.2@7620,2840 ; R354.2@7830,1994.88 7880.12,1994.88 7960,1915 R355.2@7960,1735.12 R361.2@8080,1735.12 8090,1745.12 R358.2@8090,1914.88 ; v1(7940,3100) 7940,3160 7970,3190 C134.2@8024.88,3190 ; R359.2@8034.88,2840 8010,2864.88 8010,2950 8025,2965 8037,2965 8047,2975 v1(8085,2975) ; C140.2@8474.88,1720 8474.88,1889.88 v1(8520,1935) ; C143.2@8474.88,3000 8475,3000.12 v1(8475,3100) ; C138.2@8495.12,2080 8495.12,2220.12 v1(8555,2280) 8555,2259.88 ; v1(8560,2365) 8605,2410 8605,2449.88 C137.2@8615.12,2460 C145.2@8615.12,2580 ; R365.2@8635.12,1470 8685,1470 v1(8720,1435) ; v1(8720,1940) 8744.88,1915.12 C151.2@8744.88,1720 ; C146.2@8720,2074.88 8895.12,2074.88 v1(8940,2030) ; v1(8720,2365) 8720,2425.12 C148.2@8754.88,2460 C147.2@8754.88,2580 ; v1(8925,1945) 8954.88,1974.88 C155.2@9150,1974.88 ; v1(9045,3065) 9045,2960.12 C152.2@9045.12,2960 9045.12,2800 R371.2@9075.12,2770 ; U45.14@9528.43,1440 9635.12,1440 C156.2@9640,1444.88 9946.14,1444.88 J6.2@10051.26,1550
  L6-BOT w50: 10097.96,2292.04 10097.96,2277.04 v3(10130,2245)
  L6-BOT w60: R382.2@9940,2674.88 10097.1,2517.78 10097.1,2451.8 C159.1@10097.96,2450.93 10097.96,2292.04
  other v1: 7170,1960
  other v3: 10040,2245
+5V_DIG_RAW: C158.2 J1.5 J1.6 J2.1 L7.1 R197.1 R202.2 R386.1 | length 10374
  L1-TOP w60: L7.1@10160,3740 v3(10160,3875)
  L3-Signal w50: J1.6@1315,3740 1315,3560 1415,3460 J2.1@1415,3360 ; J1.5@1315,3840 1315,3975
  L3-Signal w100: 1315,3975 1455,4115 9655,4115 9895,3875 v3(10160,3875)
  L6-BOT w60: J1.6@1315,3740 1315,3944.88 R197.1@1299.88,3960 1299.88,4029.88 1360,4090 R202.2@1404.88,4090 ; R386.1@10160,3625.12 10165.12,3630.24 C158.2@10165.12,3740 10160,3745.12 v3(10160,3875)
+5V_DIG_RTN: C158.1 J1.7 J1.8 J2.2 L7.2 R198.1 R213.2 R383.1 | length 1221.2
  L1-TOP w60: v3(9960,3745) L7.2@10050,3745
  L6-BOT w50: R198.1@1215,3624.88 R198.1@1219.88,3620 1219.88,3560.12 1275.12,3504.88 ; J2.2@1315,3360 1315,3460 1275.12,3499.88 1275.12,3504.88 ; R213.2@1660,3504.88 1275.12,3504.88
  L6-BOT w60: J1.7@1215,3840 J1.8@1215,3740 1219.88,3735.12 R198.1@1219.88,3620 ; v3(9960,3745) 10049.88,3745 C158.1@10054.88,3740 10040,3725.12 R383.1@10040,3625.12
+5V_SE: C111.1 DS3.A L5.2 R93.2 R95.2 R101.2 R108.2 R111.2 R112.2 R116.2 R118.2 R290.2 R291.2 R294.2 R297.2 R302.2 TP36.1 | length 3556.7
  L1-TOP w10: v1(4655,3210) 4655,3205 4660,3200 R93.2@4660,3115.12 ; v1(4835,3210) 4850,3195 R95.2@4850,3125.12 ; v1(5015,3210) 5040,3185 R101.2@5040,3125.12 ; v1(5195,3215) 5230,3180 R108.2@5230,3125.12 R108.2@5244.88,3125.12 ; R111.2@5320,2845.12 v1@5414.88,2845.12 ; v1@5415,2845.12 R116.2@5510,2845.12 ; R112.2@5420,3095.12 5494.88,3095.12 v1(5495,3095) 5569.88,3095 R118.2@5570,3095.12 ; DS3.A@5730,2925.12 5769.88,2925.12 5805,2890 5805,2015 L5.2@5940,1880 L5.2@5850,1880
  L1-TOP w40: v2(5780,1775) 5885,1880 L5.2@5940,1880 ; v2(5880,1770) 5945,1835 L5.2@5945,1885
  L6-BOT w10: R290.2@5320,2845.12 5414.88,2845.12 v1(5415,2845) ; v1@5415,2845.12 5500,2845.12 R294.2@5510,2855.12 ; R291.2@5420,3095.12 R297.2@5570,3095.12 ; v1@5494.88,3095.12 v1(5495,3095) ; R294.2@5509.88,2845 R294.2@5510,2845.12 ; C111.1@6030,1914.02 6030,1975 6145,2090 TP36.1@6210,2090
  L6-BOT w40: R302.2@5850,1934.88 6009.13,1934.88 C111.1@6030,1914.02
  L6-BOT w50: v2(5780,1775) 5850,1845 R302.2@5850,1934.88 ; v2(5880,1770) 5880,1775 6019.02,1914.02 C111.1@6030,1914.02
+5V_SE_RAW: C112.2 J1.1 L4.1 R202.1 R210.1 R307.1 | length 6078.9
  L1-TOP w40: L4.1@6005,3150 6030,3150 6110,3070 v2(6105,3070)
  L4-Signal w50: 6035,3145 6035,3140 v2(6105,3070)
  L4-Signal w100: v2(5735,3610) 5765,3580 5765,3415 6035,3145
  L6-BOT w40: C112.2@6000.12,3160 6005,3155.12 R307.1@6005,3045.12 6080.12,3045.12 v2(6105,3070)
  L6-BOT w50: R202.1@1515.12,4090 1750,4090
  L6-BOT w60: J1.1@1515,3840 1580,3840 1635.12,3895.12 1635.12,4059.88 1605,4090
  L6-BOT w100: 1750,4090 1775,4115 5615,4115 5735,3995 v2(5735,3610)
+5V_SE_RTN: C112.1 J1.2 L4.2 R203.1 R213.1 R306.1 | length 6356.1
  L1-TOP w40: v2(5810,3045) 5810,3055 L4.2@5905,3150
  L1-TOP w60: J1.2@1515,3740 1655,3740
  L1-TOP w100: 1655,3740 1740,3825 1740,4080 1775,4115 5615,4115 5735,3995 5735,3745 v2(5625,3635)
  L3-Signal w50: v2(5810,3045) 5885,3120
  L3-Signal w100: v2(5625,3635) 5625,3545 5675,3495 5765,3495 5765,3380 5885,3260 5885,3120
  L6-BOT w40: v2(5810,3045) 5810.12,3045.12 R306.1@5885,3045.12 5885,3155.12 C112.1@5889.88,3160
  L6-BOT w50: J1.2@1515,3740 J1.2@1520,3740 ; R213.1@1655.12,3620 R213.1@1660,3615.12
  L6-BOT w60: J1.2@1515,3740 1515,3720 1550.12,3684.88 R203.1@1550.12,3620 1555,3615.12 R213.1@1660,3615.12
+5V_WD: C165.1 DS7.A L9.2 R369.2 R380.2 R389.2 TP52.1 | length 1604.8
  L1-TOP w10: DS7.A@10332.85,1171.92 10332.85,1331.8 10332.96,1331.92 ; TP52.1@10567.97,921.92 10567.96,966.92 10617.96,1016.92 v3(10617.96,1311.92)
  L1-TOP w60: 10490,1530 v3(10490,1635)
  L6-BOT w10: v1(8842.96,1396.92) 8842.96,1266.92 8867.96,1241.92 R369.2@8867.96,1122.04 ; v1(9732.96,1401.92) 9762.96,1371.92 9762.96,1226.92 9812.96,1176.92 R380.2@9812.96,1117.04
  L6-BOT w60: R389.2@10377.96,1666.8 10458.2,1666.8 v3(10490,1635) ; C165.1@10577.96,1495.93 10577.96,1351.92 v3(10617.96,1311.92)
  other v3: 10522.96,1316.92
+5V_WD_RAW: C162.2 J1.3 L8.1 R197.2 R210.2 R391.1 | length 724.8
  L1-TOP w60: L8.1@10447.96,2781.92 10622.96,2781.92 v3(10627.96,2786.92)
  L6-BOT w50: R197.2@1410.12,3960 R197.2@1415,3955.12
  L6-BOT w60: J1.3@1415,3840 1410.12,3844.88 R197.2@1410.12,3960 R210.2@1524.88,3960 ; C162.2@10440,2760 10601.05,2760 v3(10627.96,2786.92) ; R391.1@10607.96,2667.04 10607.96,2766.92
+5V_WD_RTN: C162.1 J1.4 L8.2 R198.2 R203.2 R388.1 | length 11760.5
  L1-TOP w60: L8.2@10347.96,2781.92 10347.96,2712.04 v3(10420,2640)
  L4-Signal w50: 1415,3650 J1.4@1415,3740
  L4-Signal w75: 10315.5,3749.5 10350,3715 10610,3715 10635,3690 10635,2930 10555,2850 10555,2775 v3(10420,2640)
  L4-Signal w100: 1415,3650 1445,3620 1535,3620 1740,3825 1740,4080 1775,4115 9900,4115 10000,4015 10270,4015 10315.5,3969.5 10315.5,3749.5
  L6-BOT w60: R198.2@1330.12,3620 R203.2@1439.88,3620 1415,3644.88 J1.4@1415,3740 ; C162.1@10322.85,2777.85 C162.1@10322.85,2761.92 10325,2759.76 10325,2650 10335,2640 v3(10420,2640)
+15V: C10.2 C12.2 C16.2 C24.2 C49.2 C51.2 C74.2 C81.2 C84.2 C85.2 C93.2 C94.2 C96.2 C97.2 C98.2 C103.2 DS2.A L3.2 R46.2 R47.2 R88.2 R90.2 R99.2 R105.2 R106.2 R110.2 R119.2 R120.2 R121.2 R122.2 R195.2 R266.2 R276.2 R279.2 R283.2 R284.2 R296.2 R299.2 R304.2 R305.2 TP4.1 U1.4 U2.4 U3.4 U4.4 U5.3 U5.4 U6.4 U7.4 U8.4 U11.3 U12.3 U14.3 U15.3 U16.3 U20.3 U37.3 | length 11239
  L1-TOP w10: DS2.A@825.12,850 825.12,925.12 855,955 ; U1.4@921.57,500 980,500 v1(1000,520) ; v1(1665,970) 1690,945 1925,945 2004.65,865.35 ; v1(1845,2555) 1840,2555 1905,2620 1985,2620 2056.89,2548.11 U3.4@2186.22,2548.11 ; C10.2@1959.76,1703.11 2029.65,1703.11 2074.65,1748.11 v1(2084.65,1748.11) 2119.65,1783.11 U4.4@2166.22,1783.11 ; U2.4@2004.65,814.69 2004.65,865.35 ; 2206.89,873.11 C16.2@2239.53,873.11 ; C16.2@2239.53,903.23 C16.2@2239.53,873.11 ; U5.4@2375,563.43 U5.3@2425,563.43 2425,595 2470,640 2560,640 v1(2580,620) 2640,620 2654.88,605.12 R47.2@2730,605.12 ; v1(2915,2600) 2935.12,2620.12 R46.2@2935.12,2840 ; v1(3420,340) U6.4@3420,421.57 ; v1(3515,1240) 3545,1210 U8.4@3590,1210 ; U7.4@3516.57,2245 3565,2245 v1(3615,2295) ; R90.2@4344.88,1560 4404.88,1620 4565,1620 4585,1600 4675,1600 4720,1555 U12.3@4720,1511.57 ; v1(4365,725) 4315,675 4249.04,675 4220,704.04 4220,740 4255,775 4310,775 4387,852 4617,852 4675,910 U16.3@4731.57,910 ; R88.2@4384.88,2085 4384.88,2065.12 4420,2030 4740,2030 v1(4775,2065) ; U11.3@4441.57,1290.12 4534.88,1290.12 v1(4535,1290) ; U14.3@4671.57,2465 v1(4745,2465) ; U16.3@4695,910 4660,945 4660,1025 4750,1115 C24.2@4750,1164.88 ; R99.2@4850,454.88 4850,380 4888,342 5037,342 5065,370 5065,615 5134.88,684.88 5185.12,684.88 5210,660 5295,660 5355,720 v1(5355,730) ; R105.2@5110,914.88 5120,904.88 5294.88,904.88 5350,960 5484.88,960 R119.2@5610,834.88 5610,825 5570,785 5570,685.12 R120.2@5640.12,615 5640.12,569.88 v1(5675,535) 5735,535 5760,560 R121.2@5760,574.88 5769.88,574.88 5815,620 5815,789.88 R122.2@5800,804.88 ; R110.2@5290,890 R110.2@5290,904.88 ; 2004.65,865.35 2024.29,885 2025,885 2045,905 2207.64,905 C16.2@2239.53,873.11
  L6-BOT w10: C51.2@930,475.12 975.12,475.12 1000,500 v1(1000,520) ; C74.2@2575.12,540 2575.12,615.12 v1(2580,620) ; v1@3415,335 v1@3424.88,344.88 ; v1(3420,340) 3420,425.12 C84.2@3424.88,430 ; v1(3515,1240) 3515.12,1240.12 C85.2@3605,1240.12 ; C81.2@3525,2250.12 3570.12,2250.12 v1(3615,2295) ; R266.2@4250,1025 4294.88,1025 4360,1090.12 4360,1240.12 C94.2@4415.12,1295.24 ; C93.2@4355.12,660 4365,669.88 v1@4365,735 ; 4355.12,715.12 v1(4365,725) ; C93.2@4365.12,670 4575,670 4600,695 U37.3@4600,738.43 ; C94.2@4450,1295.24 4529.76,1295.24 v1(4535,1290) ; v1(4635,1600) 4640,1595 4680,1595 4714.88,1560.12 C96.2@4714.88,1520 ; C98.2@4680,2030.12 4714.88,2065 4805,2065 4835,2095 5064.88,2095 R283.2@5070,2089.88 ; C97.2@4680,2470.12 4739.88,2470.12 v1(4745,2465) 4910,2465 4955.12,2510.12 R276.2@4955.12,2530 ; R279.2@5005.12,490 5134.88,490 C103.2@5270,625.12 5270,655 5345,730 v1(5355,730) 5350,735 5350,955 5335,970 5140,970 5074.88,1035.12 R284.2@5074.88,1100 ; R299.2@5610,834.88 5610,825 5590,805 5590,664.88 R296.2@5640,614.88 5640,570 v1(5675,535) 5750,535 5760,545 R305.2@5760,584.88 R305.2@5730,614.88 ; R296.2@5649.88,614.88 5705,670 5705,745 5764.88,804.88 R304.2@5800,804.88
  L6-BOT w75: C49.2@800,1469.88 R195.2@990,1469.88
  other v2: 875,995 875,1065 875,1130 900,1455
+15V_RAW: C2.2 J1.9 J1.10 J2.3 L2.5 R194.1 | length 1640.5
  L1-TOP w50: L2.5@940,2683.39 965.12,2708.5 C2.2@965.12,2800 1005,2760.12 v2(1005,2715)
  L3-Signal w50: v2(1005,2715) 1005,3045 1215,3255 1215,3445 1115,3545 J1.9@1115,3840
  L6-BOT w50: R194.1@960,2575.12 960,2670 v2(1005,2715)
-5_VREF: C3.2 D1.2 R17.2 R231.1 R263.1 U5.8 U11.4 U12.4 U14.4 U15.4 U15.8 U16.4 U16.9 U20.4 U37.4 | length 17268.7
  L1-TOP w10: v1(2140,340) 2166.57,366.57 U5.8@2225,366.57 ; v1(4270,735) 4305,735 4405,835 4650,835 4675,860 U16.4@4731.57,860 ; U11.4@4441.57,1240.12 4484.88,1240.12 v1(4520,1205) ; v1(4570,1810) 4575,1810 4590,1795 4650,1795 4665,1780 4710,1780 4760,1830 U15.8@4873.43,1830 ; v1(4580,1980) U15.4@4676.57,1980 ; v1(4580,2435) 4600,2415 U14.4@4671.57,2415 ; v1(4655,640) 4705,590 4790,590 4825,625 4910.43,625 4945.43,660 4960,660 4985,685 4985,750 4975,760 U16.9@4928.43,760 U16.9@4928.43,751.57 ; U12.4@4770,1511.57 4770,1555 4795,1580 4845,1580 4905,1640 4930,1640 4945.48,1655.48 4945.48,1755.48 4980,1790 5050,1790 v1(5060,1780) ; U20.4@5270,610 5305,610 v1(5360,665)
  L1-TOP w20: C3.2@1380,2724.88 1485.04,2724.88 D1.2@1492.76,2732.6 1530,2695.35 1530,2695 1590,2695 1650,2755 ; v1(1670,2660) 1670,2665 1650,2685 1650,2835.12 R17.2@1674.88,2860 1674.88,2889.88 1715,2930 2260,2930 2325,2995 2325,3115 2325,3190 2360,3225 2435,3225 2615,3225 v1(2640,3200)
  L3-Signal w20: v1(1670,2660) 1340,2330 1340,455 1455,340 3240,340 3305,405 4275,405 4335,465 4480,465 4710,695 4835,695 4865,665 v1(5360,665) ; v1(4270,735) 4270,725 4355,640 v1(4655,640) ; v1(4520,1205) 4240,1205 3965,1480 3965,1575 4100,1710 4100,2405 4185,2490 4525,2490 v1(4580,2435) 4560,2435 4475,2350 4475,2085 v1(4580,1980) 4545,1980 4490,1925 4490,1840 4520,1810 v1(4570,1810)
  L6-BOT w10: v1(2640,3200) 2645,3200 2694.76,3150.24 R231.1@2694.76,3133.11 ; R263.1@4100,1084.88 4064.88,1084.88 4045,1065 4045,985 4095,935 4140,935 4180,895 4180,780 4225,735 v1(4270,735) ; U37.4@4650,738.43 4650,645 v1(4655,640)
  L6-BOT w20: v1(4580,1980) 4600,1960 4600,1900 4640,1860 4855,1860 4885,1830 5010,1830 5075,1765 5075,1445 5035,1405 5035,1255 5060,1230 5360,1230 5395,1195 5450,1195 5485,1230 5545,1230 5560,1215 5560,1100 5480,1020 5480,875 5430,825 5430,735 v1(5360,665)
-15V: C15.2 C23.2 C45.2 C52.2 C68.2 C71.2 C75.2 C83.2 C87.2 C91.2 C95.2 C99.2 C100.2 C101.2 C102.2 C107.2 DS1.K L1.2 R17.1 R190.2 TP2.1 U1.11 U2.11 U3.11 U4.11 U5.12 U6.11 U7.11 U8.11 U11.12 U12.12 U14.12 U15.12 U16.12 U20.12 U37.12 | length 4522.2
  L1-TOP w10: 565,960 565.12,959.88 DS1.K@565.12,860 ; v1(1030,465) 1065,500 U1.11@1118.43,500 ; U2.11@2004.65,1011.54 2004.65,930.35 v1(2005,930) 2176.42,930 C15.2@2239.53,993.11 C15.2@2229.65,993.11 ; U4.11@2363.07,1783.11 2419.65,1783.11 2444.65,1758.11 v1(2444.65,1748.11) ; U3.11@2383.07,2548.11 2384.96,2550 v1(2455,2550) ; U5.12@2425,366.57 2425,395 2490,460 v1(2495,460) ; v1(3420,535) U6.11@3420,618.43 ; v1(3615,2230) 3630,2245 U7.11@3713.43,2245 ; v1(3690,1220) 3730,1220 3745,1205 U8.11@3801.85,1205 3885,1205 3900.12,1220.12 C23.2@4015,1220.12 ; v1(4550,1350) 4609.88,1290.12 U11.12@4638.43,1290.12 ; U12.12@4720,1708.43 4720,1640 v1(4740,1620) ; v1(4775,2005) 4775,2000 4805,2030 U15.12@4873.43,2030 ; v1(4780,2410) 4780,2440 4805,2465 U14.12@4868.43,2465 ; v1(4880,1080) 4880,1060 4870,1050 4870,930 4890,910 U16.12@4928.43,910 ; v1(5365,600) 5425,660 U20.12@5458.43,660
  L1-TOP w20: R17.1@1785.12,2860 1850,2860 1865,2845 v1(1865,2760)
  L6-BOT w10: v1(1030,465) 1099.88,465 C52.2@1110,475.12 ; C68.2@2345.12,2550 v1(2455,2550) ; C71.2@2354.65,1758.23 2434.53,1758.23 v1(2444.65,1748.11) ; C75.2@2459.88,375 2495,410.12 v1(2495,460) ; v1(3420,535) 3420,605.12 C83.2@3424.88,610 ; v1(3615,2230) 3625,2230 3645.12,2250.12 C87.2@3705,2250.12 ; v1(3985,490) 3985,510 4005,530 4080,530 4121,489 4299,489 4350,540 C91.2@4355.12,540 4445.12,630 4575,630 4600,605 U37.12@4600,541.57 ; v1(4550,1350) 4604.76,1295.24 C99.2@4630,1295.24 4595.12,1330.12 ; C95.2@4714.88,1710 4714.88,1650.12 4740,1625 v1(4740,1620) ; v1(4775,2005) 4843.31,2005 C101.2@4873.43,2035.12 ; v1(4780,2410) 4784.88,2405.12 C100.2@4870,2405.12 ; v1(4880,1080) 4924.88,1080 C102.2@4950,1054.88 ; v1(5365,600) 5424.88,600 C107.2@5450,625.12
  L6-BOT w75: C45.2@440.12,1459.88 R190.2@630,1459.88
  other v2: 590,995 590,1065 590,1135 545,1459.88
-15V_RAW: C1.1 J1.13 J1.14 J2.5 L2.8 R1.1 | length 1822.4
  L1-TOP w60: R1.1@420,2565.12 420,2700 v2(450,2730) ; 555,2800 C1.1@634.88,2800 ; 561.61,2683.39 L2.8@640,2683.39 640,2794.88 C1.1@634.88,2800 ; 634.88,2869.88 C1.1@634.88,2800
  L3-Signal w50: v2(450,2880) 570,3000 670,3000 1015,3345 J2.5@1015,3360 910,3465 910,3735 J1.14@915,3740 J1.13@915,3840
  other v2: 450,2800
